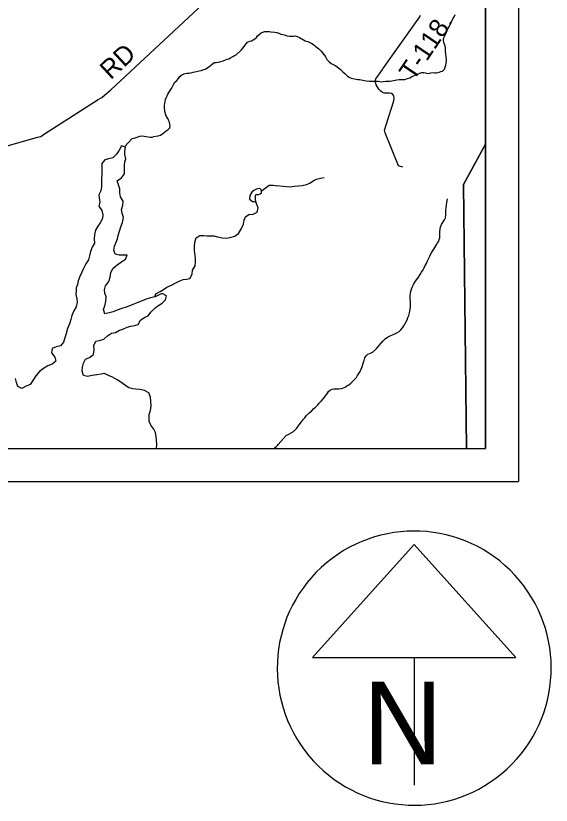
# Model space of a CAD drawing. Extents: x 0 to 34, y 0 to 22.
# Drawn here: x 7.478 to 9.099, y 13.021 to 15.409 of the extents above; entities that cross this region are included whole.
import ezdxf

# ---------------------------------------------------------------- set-up
doc = ezdxf.new("R2010")
doc.units = 0
for name, color, linetype in [('GM_X_Corporation', 7, 'Continuous'), ('GM_X_Major_Lake', 7, 'Continuous'), ('GM_X_Minor_River', 7, 'Continuous'), ('GM_X_Township_Road', 7, 'Continuous'), ('GM_X_Township_Road_Text', 7, 'Continuous'), ('SH_Data', 7, 'Continuous')]:
    doc.layers.add(name, color=color, linetype=linetype)

msp = doc.modelspace()

# ---------------------------------------------------------------- linework, layer by layer
at = {"layer": 'GM_X_Corporation'}
msp.add_lwpolyline([(2.9271, 14.1), (8.843, 14.1), (8.8335, 14.8989), (8.9, 15.0205), (8.9, 18.9286)], dxfattribs=at)
msp.add_lwpolyline([(8.843, 14.1), (8.9, 14.1), (8.9, 15.0205), (8.8335, 14.8989)], close=True, dxfattribs=at)
at = {"layer": 'GM_X_Major_Lake'}
for points in [[(7.856, 14.488), (7.869, 14.4976), (7.8786, 14.5009), (7.8864, 14.5126), (7.8976, 14.5238), (7.9083, 14.5316), (7.9214, 14.5393), (7.9314, 14.5494), (7.9343, 14.5623), (7.9215, 14.569), (7.9104, 14.5639), (7.9, 14.5591), (7.8859, 14.5559), (7.8726, 14.5516), (7.8607, 14.5468), (7.8477, 14.5417), (7.8374, 14.5377), (7.8248, 14.533), (7.8118, 14.5279), (7.7992, 14.5239), (7.7854, 14.5188), (7.7724, 14.5137), (7.7602, 14.5105), (7.7472, 14.5076), (7.7436, 14.5202), (7.7473, 14.5316), (7.7509, 14.546), (7.7511, 14.5593), (7.7479, 14.57), (7.7461, 14.5799), (7.7498, 14.5924), (7.7595, 14.6051), (7.7635, 14.6188), (7.766, 14.6324), (7.773, 14.6456), (7.7853, 14.6553), (7.7976, 14.6646), (7.8099, 14.6727), (7.8147, 14.6848), (7.8029, 14.6846), (7.7908, 14.6848), (7.7787, 14.6881), (7.7747, 14.7003), (7.7768, 14.7117), (7.7815, 14.7238), (7.7855, 14.7343), (7.7879, 14.7449), (7.7919, 14.7574), (7.7963, 14.7706), (7.8015, 14.7839), (7.8036, 14.7986), (7.8, 14.8116), (7.7979, 14.8234), (7.8019, 14.8367), (7.8029, 14.8488), (7.7951, 14.8615), (7.7927, 14.8733), (7.7925, 14.8859), (7.7885, 14.8977), (7.7853, 14.9103), (7.7976, 14.9185), (7.8069, 14.9312), (7.8067, 14.9438), (7.8069, 14.9567), (7.8086, 14.9669), (7.8107, 14.9768), (7.8086, 14.9894), (7.8084, 14.9989), (7.8097, 15.0118), (7.7984, 15.0158), (7.7913, 15.0026), (7.7832, 14.9909), (7.7716, 14.9797), (7.759, 14.9761), (7.7475, 14.9733), (7.7386, 14.962), (7.7383, 14.9415), (7.7385, 14.929), (7.7375, 14.9164), (7.7377, 14.9043), (7.7379, 14.8925), (7.7358, 14.88), (7.7295, 14.8675), (7.7301, 14.858), (7.7322, 14.8451), (7.7293, 14.8329), (7.7382, 14.8203), (7.7411, 14.8065), (7.7409, 14.7955), (7.7334, 14.7823), (7.7261, 14.7726), (7.7194, 14.7601), (7.7158, 14.7473), (7.7148, 14.7344), (7.7161, 14.7214), (7.7095, 14.709), (7.7039, 14.6965), (7.7015, 14.6833), (7.6982, 14.6712), (7.6897, 14.6584), (7.6826, 14.6448)], [(7.6826, 14.6448), (7.6782, 14.6335), (7.6723, 14.6203), (7.6668, 14.607), (7.6647, 14.5961), (7.6608, 14.5862), (7.6606, 14.5767), (7.6597, 14.5661), (7.6629, 14.5531), (7.6635, 14.5429), (7.661, 14.5288), (7.6532, 14.5168), (7.6476, 14.5021), (7.6451, 14.4899), (7.6404, 14.4775), (7.6345, 14.4631), (7.6304, 14.448), (7.626, 14.4348), (7.6228, 14.4219), (7.6131, 14.411), (7.6001, 14.4074), (7.5879, 14.4023), (7.5865, 14.3894), (7.5958, 14.3767), (7.599, 14.3641), (7.5879, 14.3548), (7.5753, 14.3497), (7.5622, 14.3419), (7.5499, 14.3326), (7.5387, 14.3199), (7.5297, 14.306), (7.5212, 14.2939), (7.5089, 14.2881), (7.4963, 14.281), (7.4838, 14.2877), (7.4799, 14.2992), (7.4774, 14.3114)], [(7.9041, 14.1), (7.9046, 14.1123), (7.9044, 14.1252), (7.9034, 14.1352), (7.9006, 14.1485), (7.8955, 14.1581), (7.8873, 14.1708), (7.8818, 14.183), (7.8817, 14.2024), (7.8857, 14.2149), (7.8875, 14.2289), (7.8873, 14.2419), (7.8856, 14.2552), (7.8805, 14.2682), (7.8677, 14.2756), (7.8548, 14.2785), (7.8416, 14.2795), (7.8321, 14.2808), (7.8204, 14.2833), (7.8102, 14.2903), (7.7963, 14.3004), (7.785, 14.3074), (7.7711, 14.3153), (7.7587, 14.3208), (7.747, 14.3267), (7.7367, 14.3253), (7.723, 14.3225), (7.7093, 14.3205), (7.6948, 14.3181), (7.6827, 14.3205), (7.6787, 14.3339), (7.68, 14.3457), (7.6833, 14.3582), (7.6892, 14.3706), (7.7014, 14.3757), (7.7137, 14.3843), (7.7151, 14.3975), (7.7145, 14.4112), (7.7201, 14.4248), (7.7319, 14.4269), (7.7445, 14.4305), (7.7557, 14.4406), (7.7679, 14.4488), (7.7794, 14.4512), (7.7924, 14.4575), (7.8023, 14.4615), (7.815, 14.4666), (7.8264, 14.4698), (7.8386, 14.4719), (7.8482, 14.4756), (7.856, 14.488)]]:
    msp.add_lwpolyline(points, dxfattribs=at)
at = {"layer": 'GM_X_Minor_River'}
for points in [[(8.793, 15.382), (8.793, 15.3878), (8.7985, 15.3929), (8.8017, 15.4005), (8.8053, 15.4065), (8.8085, 15.4128)], [(8.407, 15.2975), (8.4107, 15.2918), (8.4155, 15.2848), (8.4202, 15.2774), (8.4269, 15.2704), (8.4332, 15.265), (8.4411, 15.2606), (8.4475, 15.2577), (8.4554, 15.2515), (8.4617, 15.2464), (8.4684, 15.2397), (8.474, 15.2346), (8.4821, 15.2268), (8.4878, 15.2236), (8.4934, 15.2208), (8.4987, 15.2192), (8.504, 15.2183), (8.5135, 15.2169), (8.5188, 15.216), (8.5237, 15.2151), (8.5287, 15.2146), (8.534, 15.2134), (8.5389, 15.2125), (8.5476, 15.2115), (8.5621, 15.2111), (8.5674, 15.2114), (8.575, 15.2112), (8.5856, 15.2098), (8.5906, 15.21), (8.5986, 15.211), (8.6051, 15.2112), (8.6104, 15.2118), (8.6165, 15.2124), (8.6215, 15.213), (8.6322, 15.215), (8.6387, 15.216), (8.6448, 15.2163), (8.6562, 15.2163), (8.6643, 15.2192), (8.6712, 15.2213), (8.6762, 15.2242), (8.682, 15.2271), (8.6874, 15.2296), (8.6947, 15.2329), (8.7016, 15.2361), (8.7074, 15.2379), (8.7131, 15.2377), (8.7279, 15.2347), (8.7348, 15.2364), (8.742, 15.2377), (8.7473, 15.2368), (8.7523, 15.2363), (8.7599, 15.2384), (8.765, 15.2406), (8.7703, 15.2416), (8.7762, 15.2475), (8.7782, 15.2539), (8.7799, 15.2596), (8.7808, 15.2657), (8.7817, 15.2706), (8.7819, 15.2778), (8.7816, 15.2835), (8.78, 15.2953), (8.7794, 15.3007), (8.7795, 15.306), (8.7793, 15.3121), (8.7779, 15.3178), (8.7758, 15.3236), (8.7744, 15.3285), (8.7734, 15.3343), (8.7732, 15.34), (8.776, 15.3475), (8.7792, 15.3531), (8.782, 15.3595), (8.7844, 15.3644), (8.7877, 15.3715), (8.7913, 15.3783), (8.7949, 15.3862), (8.7973, 15.3899)], [(7.8905, 15.0422), (7.8955, 15.044), (7.902, 15.0449), (7.9092, 15.0463), (7.9158, 15.0484), (7.9227, 15.0528), (7.9336, 15.0609), (7.9394, 15.0649), (7.9445, 15.0701), (7.9458, 15.0754), (7.9448, 15.0807), (7.943, 15.0872), (7.9405, 15.0934), (7.938, 15.0988), (7.9343, 15.105), (7.9318, 15.11), (7.93, 15.1153), (7.9285, 15.1298), (7.9287, 15.1382), (7.9296, 15.1439), (7.9301, 15.1496), (7.9314, 15.156), (7.9335, 15.1613), (7.9359, 15.1669), (7.9379, 15.1718), (7.9411, 15.1774), (7.9451, 15.183), (7.9498, 15.189), (7.9526, 15.1954), (7.955, 15.201), (7.9594, 15.2081), (7.9656, 15.2137), (7.9707, 15.22), (7.9751, 15.226), (7.9805, 15.2304), (7.9875, 15.2337), (7.9955, 15.2353), (8.002, 15.2356), (8.0081, 15.2366), (8.015, 15.2387), (8.0203, 15.24), (8.0253, 15.2407), (8.033, 15.2428), (8.0395, 15.2441), (8.0476, 15.247), (8.0525, 15.248), (8.0599, 15.2531), (8.0669, 15.2575), (8.0735, 15.2634), (8.0789, 15.2675), (8.0842, 15.2677), (8.0919, 15.2686), (8.0988, 15.2711), (8.1057, 15.2729), (8.1126, 15.2757), (8.1176, 15.2779), (8.1226, 15.2793), (8.1284, 15.2822), (8.1349, 15.2858), (8.14, 15.2887), (8.1454, 15.2912), (8.1614, 15.3064), (8.1661, 15.312), (8.1712, 15.3191), (8.1755, 15.3243), (8.1798, 15.3299), (8.1864, 15.3328), (8.1913, 15.3334), (8.1967, 15.3363), (8.2018, 15.34), (8.2068, 15.3433), (8.2096, 15.3482), (8.2205, 15.3574), (8.2259, 15.3595), (8.2324, 15.3617), (8.2389, 15.3619), (8.245, 15.3617), (8.2503, 15.3604), (8.2621, 15.3601), (8.2681, 15.3592), (8.2745, 15.3564), (8.2806, 15.354), (8.2862, 15.3523), (8.2942, 15.3502), (8.2991, 15.3486), (8.3067, 15.3472), (8.312, 15.3475), (8.3185, 15.3481), (8.3253, 15.3487), (8.3325, 15.3454), (8.3374, 15.3434), (8.3494, 15.337), (8.3547, 15.3338), (8.3626, 15.3317), (8.3682, 15.3286), (8.3742, 15.325), (8.3795, 15.3222), (8.3866, 15.3167), (8.3955, 15.3092), (8.4022, 15.3022), (8.407, 15.2975)], [(7.8069, 15.0128), (7.8306, 15.0376), (7.8363, 15.0386), (7.8425, 15.0411), (7.854, 15.0454), (7.8605, 15.046), (7.8666, 15.0455), (7.8726, 15.0442), (7.8787, 15.0425), (7.8848, 15.0416), (7.8905, 15.0422)], [(8.2683, 14.8953), (8.3065, 14.8919), (8.3206, 14.8936), (8.3339, 14.8952), (8.3449, 14.8958), (8.3583, 14.899), (8.3682, 14.903), (8.3786, 14.9096), (8.3882, 14.9144), (8.4004, 14.9184), (8.4114, 14.9201)], [(8.2065, 14.8403), (8.2037, 14.8537), (8.2038, 14.8651), (8.205, 14.8681), (8.213, 14.8684), (8.2176, 14.8702), (8.2215, 14.8739), (8.2223, 14.88), (8.2198, 14.885), (8.2145, 14.8862), (8.2065, 14.8848), (8.1992, 14.8808), (8.1926, 14.8752), (8.1867, 14.8658), (8.1854, 14.8544)], [(8.2222, 14.8789), (8.2239, 14.8803), (8.2335, 14.8881), (8.2454, 14.8967), (8.2572, 14.8972), (8.2694, 14.8951)], [(7.8988, 14.5588), (7.9022, 14.5678), (7.9153, 14.5751), (7.9256, 14.5807), (7.9356, 14.5877), (7.951, 14.5954), (7.9609, 14.6002), (7.9751, 14.6075), (7.9851, 14.6108), (7.9946, 14.6118), (8.0045, 14.6139), (8.012, 14.6271), (8.0129, 14.6392), (8.0207, 14.6524), (8.0225, 14.6649), (8.0223, 14.6751), (8.0193, 14.6991), (8.0187, 14.7113), (8.0197, 14.7242), (8.0237, 14.7375), (8.0356, 14.7445), (8.047, 14.7443), (8.0565, 14.7434), (8.0683, 14.7439), (8.0778, 14.743), (8.0892, 14.7409), (8.1024, 14.7376), (8.1169, 14.7366), (8.1264, 14.7387), (8.1417, 14.7426), (8.1528, 14.7508), (8.1615, 14.7655), (8.1674, 14.7791), (8.1699, 14.7908), (8.1731, 14.8014), (8.1839, 14.808), (8.1964, 14.8093), (8.2087, 14.8148), (8.2116, 14.8281), (8.2065, 14.8403)], [(8.1854, 14.8544), (8.1952, 14.8474), (8.199, 14.8477), (8.2054, 14.8456)], [(8.7619, 14.7374), (8.7624, 14.7435), (8.7625, 14.7484), (8.7624, 14.7557), (8.7634, 14.7644), (8.7639, 14.7701), (8.7672, 14.7776), (8.7759, 14.7918), (8.7788, 14.7982), (8.7802, 14.8081), (8.7806, 14.821), (8.7816, 14.829), (8.7821, 14.8362), (8.7831, 14.8445), (8.784, 14.8495), (8.785, 14.8552)], [(8.2728, 14.1124), (8.2971, 14.1388), (8.3052, 14.1435), (8.3122, 14.1475), (8.3187, 14.1515), (8.3238, 14.1559), (8.3289, 14.1611), (8.3361, 14.1712), (8.3432, 14.1809), (8.3491, 14.1883), (8.3531, 14.1932), (8.357, 14.1984), (8.366, 14.208), (8.373, 14.2132), (8.3809, 14.2213), (8.386, 14.2254), (8.3922, 14.232), (8.397, 14.2369), (8.4029, 14.2435), (8.4099, 14.2517), (8.4163, 14.2599), (8.4214, 14.267), (8.425, 14.2726), (8.4305, 14.277), (8.4355, 14.2795), (8.4412, 14.2805), (8.4492, 14.2803), (8.4561, 14.2805), (8.4641, 14.2818), (8.4699, 14.2831), (8.4749, 14.2856), (8.4807, 14.2893), (8.4862, 14.2929), (8.4924, 14.2977), (8.4987, 14.3036), (8.5049, 14.3099), (8.5096, 14.3151), (8.5128, 14.3203), (8.5168, 14.3271), (8.5208, 14.3334), (8.5241, 14.3406), (8.5265, 14.3462), (8.5282, 14.3511), (8.5303, 14.3579), (8.5328, 14.3662), (8.5353, 14.3745), (8.5385, 14.3805), (8.5436, 14.3853), (8.5486, 14.3875), (8.554, 14.3896), (8.5598, 14.3929), (8.5653, 14.3973), (8.5716, 14.4036), (8.5779, 14.4114), (8.583, 14.4173), (8.5893, 14.4244), (8.5963, 14.4314), (8.6033, 14.4365), (8.6134, 14.4416), (8.6184, 14.4437), (8.6234, 14.4459), (8.6315, 14.4498), (8.6385, 14.4542), (8.644, 14.459), (8.6491, 14.4653), (8.6531, 14.4713), (8.6571, 14.478), (8.6631, 14.4897), (8.6652, 14.4961), (8.668, 14.5021), (8.6702, 14.5104), (8.673, 14.5278), (8.6732, 14.5358), (8.6727, 14.545), (8.6721, 14.5519), (8.6724, 14.5625), (8.673, 14.5693), (8.6747, 14.5762), (8.6764, 14.5818), (8.6793, 14.5905), (8.6821, 14.5965), (8.6885, 14.6062), (8.692, 14.6114), (8.6972, 14.6185), (8.7028, 14.6268), (8.7067, 14.6331), (8.7111, 14.6406), (8.7144, 14.6462), (8.718, 14.6534), (8.7216, 14.6601), (8.7249, 14.668), (8.7285, 14.6755), (8.7314, 14.6819), (8.7338, 14.6868), (8.7382, 14.6943), (8.7438, 14.7033), (8.7533, 14.7178), (8.7554, 14.7227), (8.7585, 14.7276), (8.7598, 14.7325), (8.7619, 14.7374)], [(8.261, 14.1), (8.2643, 14.1038), (8.2674, 14.1064), (8.2708, 14.1094), (8.2728, 14.1124)]]:
    msp.add_lwpolyline(points, dxfattribs=at)
at = {"layer": 'GM_X_Township_Road'}
for points in [[(7.4124, 15.0048), (7.5436, 15.0417), (7.5533, 15.0445), (7.5615, 15.05), (7.7278, 15.156), (7.7386, 15.1623), (7.7463, 15.1686), (7.7654, 15.1857), (8.1779, 15.57), (8.2055, 15.5951), (8.2191, 15.6084), (8.2391, 15.6325), (8.2489, 15.6435), (8.2583, 15.655), (8.2679, 15.6699), (8.2752, 15.6869)], [(8.5882, 15.247), (8.5893, 15.2487), (8.7011, 15.4066), (8.7038, 15.4108)], [(8.6496, 14.9514), (8.6364, 14.9551), (8.5968, 15.0548), (8.5957, 15.059), (8.5949, 15.0635), (8.5964, 15.0696), (8.5991, 15.0791), (8.6229, 15.152), (8.624, 15.1607), (8.6228, 15.1668), (8.6198, 15.1713), (8.616, 15.1743), (8.6096, 15.1755), (8.6001, 15.1751), (8.5944, 15.1754), (8.588, 15.1773), (8.583, 15.1811), (8.5777, 15.1871), (8.5694, 15.2008), (8.5671, 15.2076), (8.5667, 15.2137), (8.5682, 15.2186), (8.5743, 15.2262), (8.5882, 15.247)]]:
    msp.add_lwpolyline(points, dxfattribs=at)
at = {"layer": 'SH_Data'}
for p, q in [((9, 21), (9, 14)), ((8.9, 20.9), (8.9, 14.1)), ((2.1, 14.1), (8.9, 14.1)), ((2, 14), (9, 14)), ((8.6845, 13.8091), (8.3769, 13.4678)), ((8.9921, 13.4678), (8.6845, 13.8091)), ((8.3769, 13.4678), (8.9921, 13.4678)), ((8.6845, 13.4678), (8.6845, 13.0811)), ((8.6845, 13.4353), (8.6845, 13.4353)), ((8.6845, 13.4353), (8.6845, 13.4353))]:
    msp.add_line(p, q, dxfattribs=at)
msp.add_arc((8.6845, 13.4353), 0.4148, 129.7798, 129.7633, dxfattribs=at)

# ---------------------------------------------------------------- texts
at = {"layer": 'GM_X_Township_Road_Text'}
for s, rotation, p in [('T-118', 55.9989, (8.6821, 15.2098)), ('RD', 42.9045, (7.7651, 15.2138))]:
    msp.add_text(s, height=0.05682, rotation=rotation, dxfattribs=at).set_placement(p)
at = {"layer": 'SH_Data'}
msp.add_text('N', height=0.25, dxfattribs=at).set_placement((8.5292, 13.144))

doc.saveas('drawing.dxf')
